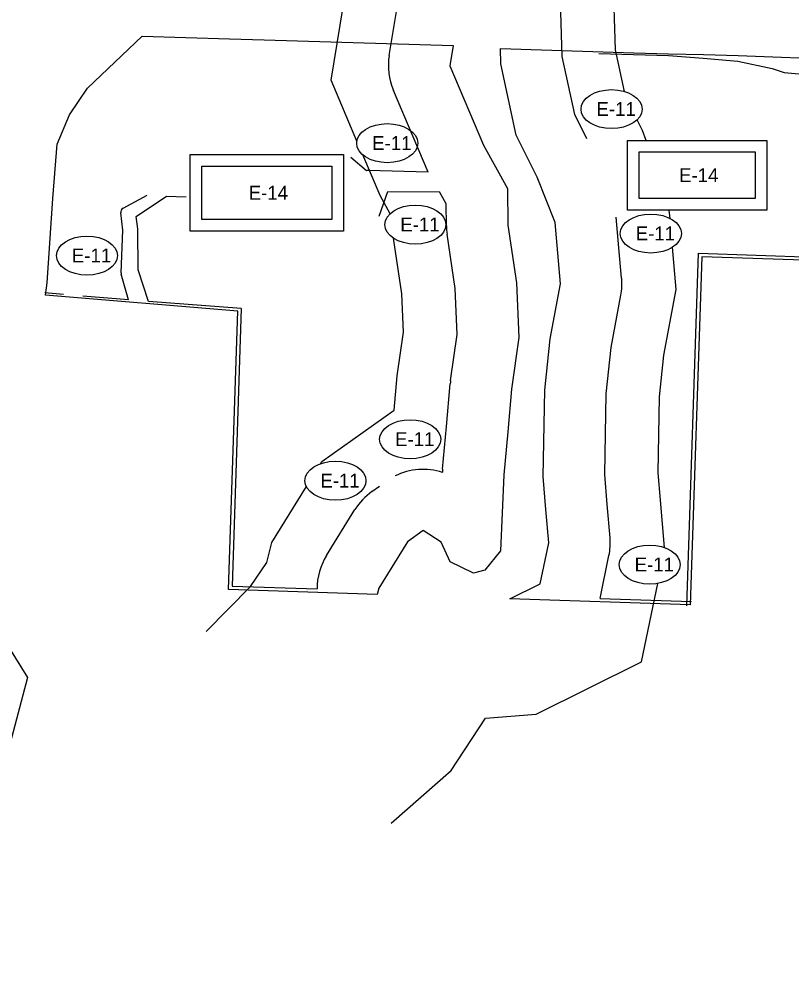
# Model space of a CAD drawing. Extents: x 977239 to 983725, y 1525948 to 1526901.
# Drawn here: x 977835.8 to 978168.6, y 1526083.4 to 1526495.3 of the extents above; entities that cross this region are included whole.
import ezdxf

# ---------------------------------------------------------------- set-up
doc = ezdxf.new("R2010")
doc.units = 0
for name, color, linetype in [('R_Erosion', 7, 'Continuous'), ('R_No Plot', 7, 'Continuous'), ('R_Water', 7, 'Continuous')]:
    doc.layers.add(name, color=color, linetype=linetype)

msp = doc.modelspace()

# ---------------------------------------------------------------- linework, layer by layer
at = {"layer": 'R_Erosion'}
for p, q in [((977995.22, 1526479.66), (978002.72, 1526524.9)), ((978012.01, 1526429.43), (977997.01, 1526464.67)), ((977985.4, 1526430), (977978.75, 1526435.83)), ((978012.01, 1526429.43), (977986.17, 1526430.13)), ((977880.61, 1526413.92), (977891, 1526419.5)), ((977899.37, 1526419.09), (977907.7, 1526418.86)), ((978019.7, 1526415.78), (978016.85, 1526420.98)), ((978123.34, 1526242.68), (978128.43, 1526394.59)), ((978128.43, 1526394.59), (978743.95, 1526373.96)), ((977854.95, 1526376.85), (977846.97, 1526377.47)), ((977882.94, 1526374.55), (977863.32, 1526376.07)), ((977931.52, 1526370.72), (977891.57, 1526373.81)), ((977931.52, 1526370.72), (977927.52, 1526251.24)), ((978018.14, 1526300.21), (978018.15, 1526300.33)), ((977987.77, 1526291.97), (977990.97, 1526294.24)), ((977968.21, 1526264.41), (977980.48, 1526284.19)), ((978086.04, 1526245.93), (978089.86, 1526264.39)), ((977927.52, 1526251.24), (977964.16, 1526250.01)), ((978086.04, 1526245.93), (978125.41, 1526244.61))]:
    msp.add_line(p, q, dxfattribs=at)
for points in [[(978080.34, 1526443.84), (978075.14, 1526454.21), (978069.68, 1526479.32), (978068.59, 1526517.53), (978070.92, 1526523.88), (978087.43, 1526556.02)], [(977886.9, 1526405.07), (977886.22, 1526410.31), (977899.37, 1526419.09)], [(977990.9, 1526410.46), (977994.65, 1526421.18), (978016.85, 1526420.98)], [(978019.83, 1526406.29), (978019.7, 1526415.78)], [(977879.77, 1526386.12), (977880.49, 1526404.52), (977879.57, 1526411.91)], [(978095.33, 1526383.81), (978094.18, 1526396.92), (978093.02, 1526410.04)], [(977891.57, 1526373.81), (977887.14, 1526387.4), (977886.91, 1526404.84)], [(978021.67, 1526339.8), (978024.48, 1526359.5), (978023.58, 1526379.34), (978020.12, 1526402.72)], [(977882.94, 1526374.55), (977879.84, 1526385.49)], [(978090.33, 1526272.09), (978089.14, 1526286.38), (978088.07, 1526299.32), (978088.7, 1526334.04), (978090.74, 1526353.92), (978094.97, 1526376.44)], [(978018.23, 1526301.53), (978019.87, 1526319.95), (978021.5, 1526338.37)]]:
    msp.add_lwpolyline(points, dxfattribs=at)
for points in [[(978097.9, 1526443.15), (978157.9, 1526443.15), (978157.9, 1526413.15), (978097.9, 1526413.15)], [(978102.9, 1526438.15), (978152.9, 1526438.15), (978152.9, 1526418.15), (978102.9, 1526418.15)], [(977909.54, 1526437.09), (977975.54, 1526437.09), (977975.54, 1526404.09), (977909.54, 1526404.09)], [(977914.54, 1526432.09), (977970.54, 1526432.09), (977970.54, 1526409.09), (977914.54, 1526409.09)]]:
    msp.add_lwpolyline(points, close=True, dxfattribs=at)
for centre, radius, start, end in [((978021.86, 1526475.24), 27, 170.5872, 203.0489), ((977986.11, 1526428.13), 2, 88.443, 110.9383), ((977881.56, 1526412.16), 2, 118.2469, 187.1054), ((977884.92, 1526404.81), 2, 0.7331, 7.3484), ((978046.83, 1526406.67), 27, 180.8142, 188.4243), ((977881.77, 1526386.04), 2, 177.7361, 195.823), ((978068.44, 1526381.43), 27, 349.3528, 5.0451), ((978048.4, 1526335.98), 27, 171.88, 174.9225), ((978009.83, 1526274.52), 27, 72.0653, 116.6345), ((978045.12, 1526299.14), 27, 174.9194, 177.4635), ((978003.43, 1526269.97), 27, 125.4334, 148.2075), ((978063.42, 1526269.86), 27, 348.3132, 4.7431), ((977991.16, 1526250.18), 27, 148.2075, 180.3608)]:
    msp.add_arc(centre, radius, start, end, dxfattribs=at)
for centre in [(978090.97, 1526456.59), (977994.37, 1526441.94), (978006.49, 1526406.88), (978107.88, 1526403.04), (977865.04, 1526393.52), (978004.24, 1526314.45), (977972.07, 1526296.61), (978107.4, 1526260.49)]:
    msp.add_ellipse(centre, major_axis=(13.15, 0), ratio=0.638788, dxfattribs=at)
at = {"layer": 'R_No Plot'}
for p, q in [((978043.08, 1526482.68), (978100.53, 1526480.86)), ((978085.49, 1526480.53), (978100.49, 1526480.05)), ((978100.49, 1526480.05), (978115.47, 1526479.64)), ((978100.53, 1526480.86), (978115.53, 1526480.47)), ((978115.47, 1526479.64), (978130.42, 1526478.59)), ((978115.53, 1526480.47), (978130.51, 1526480.06)), ((978130.51, 1526480.06), (978145.5, 1526479.64)), ((978145.5, 1526479.64), (978160.49, 1526479.09)), ((978130.42, 1526478.59), (978145.34, 1526477.31)), ((978145.34, 1526477.31), (978160.18, 1526474.07)), ((978160.49, 1526479.09), (978175.48, 1526478.58)), ((978160.18, 1526474.07), (978165.3, 1526472.32)), ((978165.3, 1526472.32), (978180.33, 1526470.98)), ((978129.88, 1526393.04), (978124.86, 1526243.13)), ((978846.06, 1526369.04), (978129.88, 1526393.04)), ((977929.98, 1526369.6), (977847.16, 1526376.54)), ((977925.97, 1526249.79), (977929.98, 1526369.6)), ((977990, 1526247.65), (977925.97, 1526249.79)), ((978124.86, 1526243.13), (978047.12, 1526245.73)), ((977821.7, 1526240.25), (977839.49, 1526211.96)), ((977839.49, 1526211.96), (977805.27, 1526083.44))]:
    msp.add_line(p, q, dxfattribs=at)
for points in [[(977847.16, 1526376.54), (977847.9, 1526381.86), (977850.31, 1526418.17), (977852.19, 1526441.52), (977857.47, 1526454.11), (977865.26, 1526465.68), (977888.89, 1526488.04)], [(977888.89, 1526488.04), (977926.43, 1526486.89), (977941.42, 1526486.42), (978022.8, 1526483.98)], [(978022.8, 1526483.98), (978021.34, 1526475.18), (978035.85, 1526441.08), (978046.11, 1526422.37), (978046.33, 1526406.63), (978050, 1526381.88), (978051.06, 1526358.22), (978047.9, 1526336.04), (978046.26, 1526317.6), (978044.62, 1526299.17), (978043.17, 1526266.41), (978036.39, 1526258.04), (978031.45, 1526256.77), (978021.42, 1526261.73), (978017.66, 1526270.21), (978009.81, 1526275.12), (978003.05, 1526270.32), (977990.7, 1526250.38), (977990, 1526247.65)], [(978047.12, 1526245.73), (978060.3, 1526252.29), (978063.93, 1526269.83), (978062.73, 1526284.19), (978061.55, 1526298.46), (978062.22, 1526335.64), (978064.49, 1526357.73), (978068.94, 1526381.41), (978067.78, 1526394.59), (978066.62, 1526407.78), (978058.99, 1526427.29), (978049.96, 1526445.32), (978043.27, 1526476.1), (978043.08, 1526482.68)]]:
    msp.add_lwpolyline(points, dxfattribs=at)
for centre in [(978090.97, 1526456.59), (977994.37, 1526441.94), (978006.49, 1526406.88), (978107.88, 1526403.04), (977865.04, 1526393.52), (978004.24, 1526314.45), (977972.07, 1526296.61), (978107.4, 1526260.49)]:
    msp.add_ellipse(centre, major_axis=(13.15, 0), ratio=0.638788, dxfattribs=at)
at = {"layer": 'R_Water'}
for points in [[(978096.51, 1526464.21), (978092.61, 1526482.11), (978091.71, 1526513.77), (978092.03, 1526514.63), (978111.2, 1526551.94), (978113.09, 1526564.05)], [(977981.3, 1526442.85), (977970.15, 1526469.06), (977978.03, 1526516.57)], [(978105.94, 1526443.15), (978104.27, 1526447.43), (978101.98, 1526451.99)], [(977995.58, 1526411.57), (977991.26, 1526419.44), (977983.83, 1526436.92)], [(978116.15, 1526409.56), (978115.83, 1526413.15)], [(977965.66, 1526303.94), (977966.23, 1526304.87), (977997.41, 1526327.05), (977998.71, 1526341.73), (978001.4, 1526360.62), (978000.66, 1526377.13), (977997.13, 1526400.98)], [(978113.76, 1526267.84), (978112.06, 1526288.28), (978111.09, 1526300.07), (978111.68, 1526332.66), (978113.52, 1526350.62), (978118.85, 1526378.97), (978117.25, 1526397.14)], [(977916.43, 1526231.67), (977935.49, 1526251.08), (977942.44, 1526261.45), (977944.6, 1526269.97), (977959.54, 1526294.07)], [(977995.99, 1526149.24), (978021.93, 1526171.84), (978036.73, 1526194.32), (978058.49, 1526196.1), (978103.9, 1526218.7), (978110.87, 1526252.39)]]:
    msp.add_lwpolyline(points, dxfattribs=at)

# ---------------------------------------------------------------- texts
at = {"layer": 'R_Erosion'}
for s, height, p in [('E-11', 5.999, (978084.47, 1526453.64)), ('E-11', 5.999, (977987.87, 1526438.99)), ('E-14', 6, (978120.05, 1526425.15)), ('E-14', 6, (977934.7, 1526417.59)), ('E-11', 5.999, (977999.99, 1526403.93)), ('E-11', 5.999, (978101.38, 1526400.09)), ('E-11', 5.999, (977858.54, 1526390.57)), ('E-11', 5.999, (977997.75, 1526311.5)), ('E-11', 5.999, (977965.57, 1526293.66)), ('E-11', 5.999, (978100.9, 1526257.54))]:
    msp.add_text(s, height=height, dxfattribs=at).set_placement(p)

doc.saveas('drawing.dxf')
